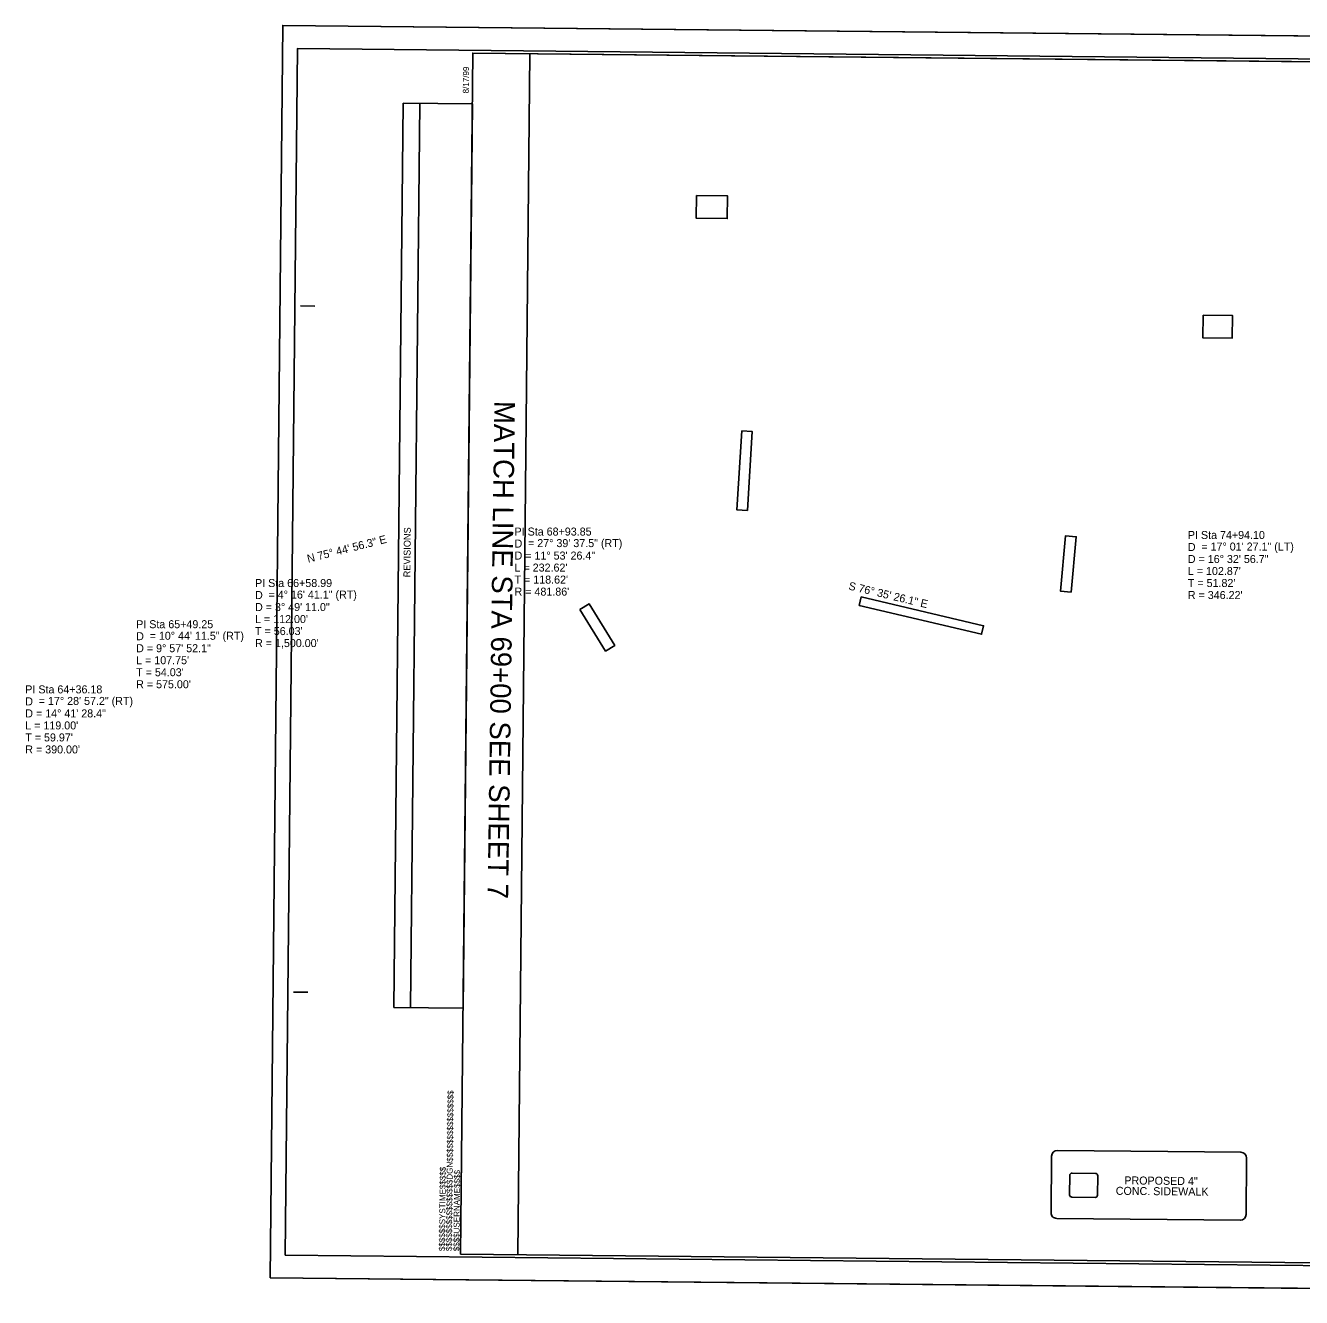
# Model space of a CAD drawing. Extents: x 928111 to 937215, y 684176 to 686530.
# Drawn here: x 932751 to 933867, y 684176 to 685288 of the extents above; entities that cross this region are included whole.
import ezdxf

# ---------------------------------------------------------------- set-up
doc = ezdxf.new("R2010")
doc.units = 0
for name, color, linetype in [('Exist Horizontal Alignment Curve and Spiral Data', 7, 'Continuous'), ('Exist Horizontal Alignment Direction Label', 7, 'Continuous'), ('Matchline', 7, 'Continuous'), ('Matchline Text', 7, 'Continuous'), ('Old_Level_2', 7, 'Continuous'), ('Prop DSN Text', 7, 'Continuous'), ('Sheet Cutting Line CELL', 7, 'Continuous'), ('Sheet Layout Plan Border', 7, 'Continuous'), ('Sheet Plan CELL', 7, 'Continuous'), ('Sheet Plan Layout CELL', 7, 'Continuous'), ('Sheet Plot Border Inside CELL', 7, 'Continuous'), ('Sheet Plot Border Outside CELL', 7, 'Continuous')]:
    doc.layers.add(name, color=color, linetype=linetype)

msp = doc.modelspace()

# ---------------------------------------------------------------- linework, layer by layer
at = {"layer": 'Matchline'}
msp.add_line((933181.8, 684213.3), (933192.5, 685263.2), dxfattribs=at)
at = {"layer": 'Old_Level_2'}
for p, q in [((933664.7, 684282.6), (933664.6, 684265.5)), ((933687.1, 684284.3), (933666.8, 684284.5)), ((933688.9, 684265.3), (933689.1, 684282.3)), ((933666.5, 684263.5), (933686.9, 684263.3))]:
    msp.add_line(p, q, dxfattribs=at)
for centre, start, end in [((933666.7, 684282.5), 89.4141, 179.4141), ((933687.1, 684282.3), 359.4141, 89.4141), ((933666.6, 684265.5), 179.4141, 269.4141), ((933686.9, 684265.3), 269.4141, 359.4141)]:
    msp.add_arc(centre, 2, start, end, dxfattribs=at)
at = {"layer": 'Prop DSN Text'}
for p, q in [((933648.8, 684299.4), (933648.3, 684250)), ((933648.3, 684250), (933648.8, 684299.4)), ((933814.5, 684302.8), (933653.9, 684304.4)), ((933653.9, 684304.4), (933814.5, 684302.8)), ((933818.9, 684248.2), (933819.4, 684297.7)), ((933819.4, 684297.7), (933818.9, 684248.2)), ((933653.3, 684244.9), (933813.9, 684243.3)), ((933813.9, 684243.3), (933653.3, 684244.9))]:
    msp.add_line(p, q, dxfattribs=at)
for points in [[(933338.2, 685139.3), (933365.3, 685139), (933365.1, 685119.2), (933338, 685119.5)], [(933781.3, 685034.7), (933807.1, 685034.4), (933806.9, 685014.7), (933781, 685014.9)], [(933382.7, 684863.8), (933387, 684932.9), (933377.9, 684933.5), (933373.5, 684864.4)], [(933665.9, 684792.6), (933670.3, 684840.9), (933660.9, 684841.7), (933656.5, 684793.5)], [(933480.6, 684780.8), (933587.6, 684755.7), (933589.3, 684763.2), (933482.3, 684788.4)], [(933236.1, 684777.4), (933258.6, 684741), (933266.6, 684746), (933244.2, 684782.4)]]:
    msp.add_lwpolyline(points, close=True, dxfattribs=at)
for centre, start, end in [((933653.8, 684299.4), 89.4141, 179.4141), ((933653.8, 684299.4), 89.4141, 179.4141), ((933814.4, 684297.8), 359.4141, 89.4141), ((933814.4, 684297.8), 359.4141, 89.4141), ((933653.3, 684249.9), 179.4141, 269.4141), ((933653.3, 684249.9), 179.4141, 269.4141), ((933813.9, 684248.3), 269.4141, 359.4141), ((933813.9, 684248.3), 269.4141, 359.4141)]:
    msp.add_arc(centre, 5, start, end, dxfattribs=at)
at = {"layer": 'Sheet Cutting Line CELL'}
for p, q in [((932976.3, 685288), (932965.1, 684193)), ((934659.7, 685270.7), (932976.3, 685288)), ((932965.1, 684193), (934648.5, 684175.8))]:
    msp.add_line(p, q, dxfattribs=at)
at = {"layer": 'Sheet Layout Plan Border'}
msp.add_line((933181.8, 684213.3), (933192.5, 685263.3), dxfattribs=at)
at = {"layer": 'Sheet Plan CELL'}
for p, q in [((933142.5, 685263.8), (933142.5, 685263.8)), ((933088, 684429.3), (933096.1, 685219.9)), ((932991.8, 685042.8), (933004.3, 685042.7)), ((932985.7, 684442.8), (932998.2, 684442.7)), ((933131.8, 684213.8), (933131.8, 684213.8))]:
    msp.add_line(p, q, dxfattribs=at)
for points in [[(934642.5, 685248.4), (933142.5, 685263.8), (933131.8, 684213.8), (934631.7, 684198.5)], [(933073.5, 684429.4), (933081.6, 685220), (933142.1, 685219.4), (933134, 684428.8)]]:
    msp.add_lwpolyline(points, close=True, dxfattribs=at)
at = {"layer": 'Sheet Plan Layout CELL'}
msp.add_lwpolyline([(933142.5, 685263.7), (933131.8, 684213.8), (934631.7, 684198.5), (934640.3, 685037), (934401.1, 685039.4), (934403.2, 685250.9)], close=True, dxfattribs=at)
at = {"layer": 'Sheet Plot Border Inside CELL'}
msp.add_lwpolyline([(932978.3, 684212.9), (934644.2, 684195.9), (934655, 685250.8), (932989.1, 685267.8)], close=True, dxfattribs=at)
at = {"layer": 'Sheet Plot Border Outside CELL'}
msp.add_lwpolyline([(932965.1, 684193), (934648.5, 684175.8), (934659.7, 685270.7), (932976.3, 685288)], close=True, dxfattribs=at)

# ---------------------------------------------------------------- texts
at = {"layer": 'Exist Horizontal Alignment Curve and Spiral Data'}
for s, p in [('PI Sta 68+93.85', (933179, 684842)), ('PI Sta 74+94.10', (933768, 684839)), ('D', (933179, 684831.5)), ('= 27%%d 39\' 37.5" (RT)', (933190.8, 684831.9)), ('D', (933768, 684828.5)), ('= 17%%d 01\' 27.1" (LT)', (933779.8, 684828.9)), ('D = 11%%d 53\' 26.4"', (933179, 684821)), ('D = 16%%d 32\' 56.7"', (933768, 684818)), ("L = 232.62'", (933179, 684810.5)), ("L = 102.87'", (933768, 684807.5)), ('PI Sta 66+58.99', (932952, 684797)), ("T = 118.62'", (933179, 684800)), ("T = 51.82'", (933768, 684797)), ('D', (932952, 684786.5)), ('= 4%%d 16\' 41.1" (RT)', (932963.8, 684786.9)), ("R = 481.86'", (933179, 684789.5)), ("R = 346.22'", (933768, 684786.5)), ('D = 3%%d 49\' 11.0"', (932952, 684776)), ('PI Sta 65+49.25', (932848, 684761)), ("L = 112.00'", (932952, 684765.5)), ('D', (932848, 684750.5)), ('= 10%%d 44\' 11.5" (RT)', (932859.8, 684750.9)), ("T = 56.03'", (932952, 684755)), ('D = 9%%d 57\' 52.1"', (932848, 684740)), ("R = 1,500.00'", (932952, 684744.5)), ("L = 107.75'", (932848, 684729.5)), ("T = 54.03'", (932848, 684719)), ('PI Sta 64+36.18', (932751, 684704)), ("R = 575.00'", (932848, 684708.5)), ('D', (932751, 684693.5)), ('= 17%%d 28\' 57.2" (RT)', (932762.8, 684693.9)), ('D = 14%%d 41\' 28.4"', (932751, 684683)), ("L = 119.00'", (932751, 684672.5)), ("T = 59.97'", (932751, 684662)), ("R = 390.00'", (932751, 684651.5))]:
    msp.add_text(s, height=7, dxfattribs=at).set_placement(p)
at = {"layer": 'Exist Horizontal Alignment Direction Label'}
for s, rotation, p in [('N 75%%d 44\' 56.3" E', 14.251, (932998.5, 684818.2)), ('S 76%%d 35\' 26.1" E', 346.5906, (933470.7, 684794.9))]:
    msp.add_text(s, height=7, rotation=rotation, dxfattribs=at).set_placement(p)
at = {"layer": 'Matchline Text'}
msp.add_text('MATCH LINE STA 69+00 SEE SHEET 7', height=18, rotation=269.207, dxfattribs=at).set_placement((933161.4, 684959.8))
at = {"layer": 'Prop DSN Text'}
for s, p in [('PROPOSED 4"', (933712.4, 684274.7)), ('CONC. SIDEWALK', (933704.9, 684265.6))]:
    msp.add_text(s, height=7, rotation=359.4141, dxfattribs=at).set_placement(p)
at = {"layer": 'Sheet Plan CELL'}
for s, height, p in [('8/17/99', 5.25, (933139, 685228.6)), ('REVISIONS', 6, (933087.8, 684805.5)), ('$$$$$$$$$$$$$$$$DGN$$$$$$$$$$$$$$$$', 5.25, (933124.2, 684216.3)), ('$$$$$$SYSTIME$$$$$', 5.25, (933118.1, 684216.3)), ('$$$$USERNAME$$$$', 5.25, (933130.7, 684216.2))]:
    msp.add_text(s, height=height, rotation=89.4141, dxfattribs=at).set_placement(p)

doc.saveas('drawing.dxf')
